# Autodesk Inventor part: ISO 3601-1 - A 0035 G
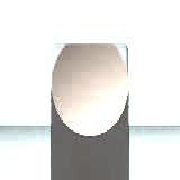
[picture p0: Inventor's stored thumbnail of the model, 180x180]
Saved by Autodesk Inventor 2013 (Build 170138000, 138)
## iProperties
Created: 2007-03
Part Number: ISO 3601-1 - A 0035 G
Material: Caoutchouc
Description: Systèmes hydrauliques - Joint torique
Document SubType Name: Modeling
Standard: ISO 3601-1
Designer: Laur
Standard Revision: Troisième édition 2002-08-01
Standards Organization: ISO
Language: fr-FR
Size Designation: A 0035 G
Categories: <MemberInstance><Categories><Category DisplayName="Pièces d'arbre" InternalName="7f7aeb1f-a693-4053-b835-cee3144e0d98" Mnemonic="SHFT"><Category DisplayName="Et
Density: 1 g/cm^3
IsCustomPart: 0
Author: Laur
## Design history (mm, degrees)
revolve "Corps" stored, may be unused: angle "d19" = 90 deg
node "Solide1"
node "Corps solides"
node "Corps surfaciques"
sketch "Esquisse1"
  geometry: L1 (-0.011, 0)-(-0.011, 0); L2 (-0.566, 1.4)-(0.566, 1.4); L3 (-0.566, 0)-(0.566, 0); L4 (-4, -2)-(6.034, -2); L5 (-6.007, 0)-(8.04, 0) reference; L6 (0, 4.64)-(0, -12.44) reference; A1 r 0.9 centre (0, 0.7) between (-0.566, 1.4) and (-0.566, 0); A2 r 0.9 centre (0, 0.7) between (0.566, 0) and (0.566, 1.4)
  constraints: 8 end point, 4 point on circle, 2 centre point, 2 horizontal alignment, 2 parallel, 1 coincident, 1 horizontal, 1 point on line, 1 other
  dimensions: "d0" = 4 diameter of L5 L4 (= NND); "d1" = 0.7 distance from line of A1.centre L2 (= -0.25 x NND + 0.25 x NDOR); "d2" = 0.9 radius of A1 (= 0.5 x QDM); "d3" = 0.7 distance from line of L3 A1.centre (= -0.25 x NND + 0.25 x NDOR); "d4" = 1.4 distance between parallel lines of L5 L2 (= -0.5 x NND + 0.5 x NDOR)
other parameters: "QDM" = 1.8 [user parameter; used in 1 equation term], "NND" = 4 [user parameter; used in 5 equation terms], "NDOR" = 6.8 [user parameter; used in 3 equation terms], "d5" = 0, "R2" = 0.2 [user parameter], "SD1" = 3.5 [user parameter], "R1" = 0.3 [user parameter], "NB2" = 3.8 [user parameter], "NB1" = 2.4 [user parameter], "NB3" = 5.2 [user parameter], "BD" = 4 (= NND) [user parameter]
